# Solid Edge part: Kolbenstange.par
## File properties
Last saved by: bmolnar
Revision: 76
Dokumentum tartalom típus: 0
Sűrűség: 0,000 kg/m^3
Pontosság: 0,990
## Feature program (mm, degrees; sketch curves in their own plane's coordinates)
base feature "unnamed BaseFeature 1"
thread "unnamed Thread 1"
sketch for "unnamed Protrusion 1" plane through (0, 0, -18.5) normal (0, 0, -1) x-axis (0, -1, 0)
  circle centre (0, 0) radius 12.5
extrude "unnamed Protrusion 1" add finite 14 along +normal
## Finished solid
Body 1: solid body, 17 faces, 23 edges, 8 vertices.
  Faces by surface: plane 8, cylinder 4, torus 3, cone 2
  Edges by curve: circle 13, line 6, ellipse 2, intersection 2
Bounding box of the edges (mm; curved faces can reach further): 25.000 x 25.000 x 53.500, from (-12.5, -12.5, -32.5) to (12.5, 12.5, 21).
Cylindrical faces by radius (mm): R2.9 x1, R4 x1, R5 x1, R12.5 x1
Conical faces (half-angle, radius in mm at the cone's reference point): 20 deg R3.5 x1, 60 deg R3.55 x1
Toroidal faces (ring radius, tube radius in mm): R3.3 r0.4 x2, R3.8 r1.2 x1
Planar faces by outward normal: +x 1, +z 3, -x 1, -z 1, oblique 2
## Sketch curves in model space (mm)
circle centre (0, 0, -18.5) radius 12.5
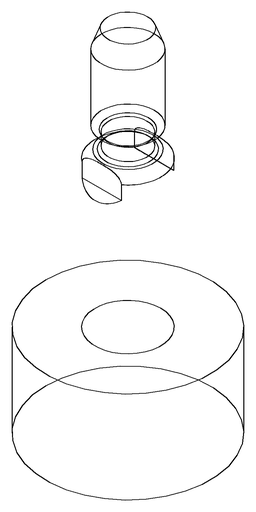
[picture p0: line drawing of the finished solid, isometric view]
